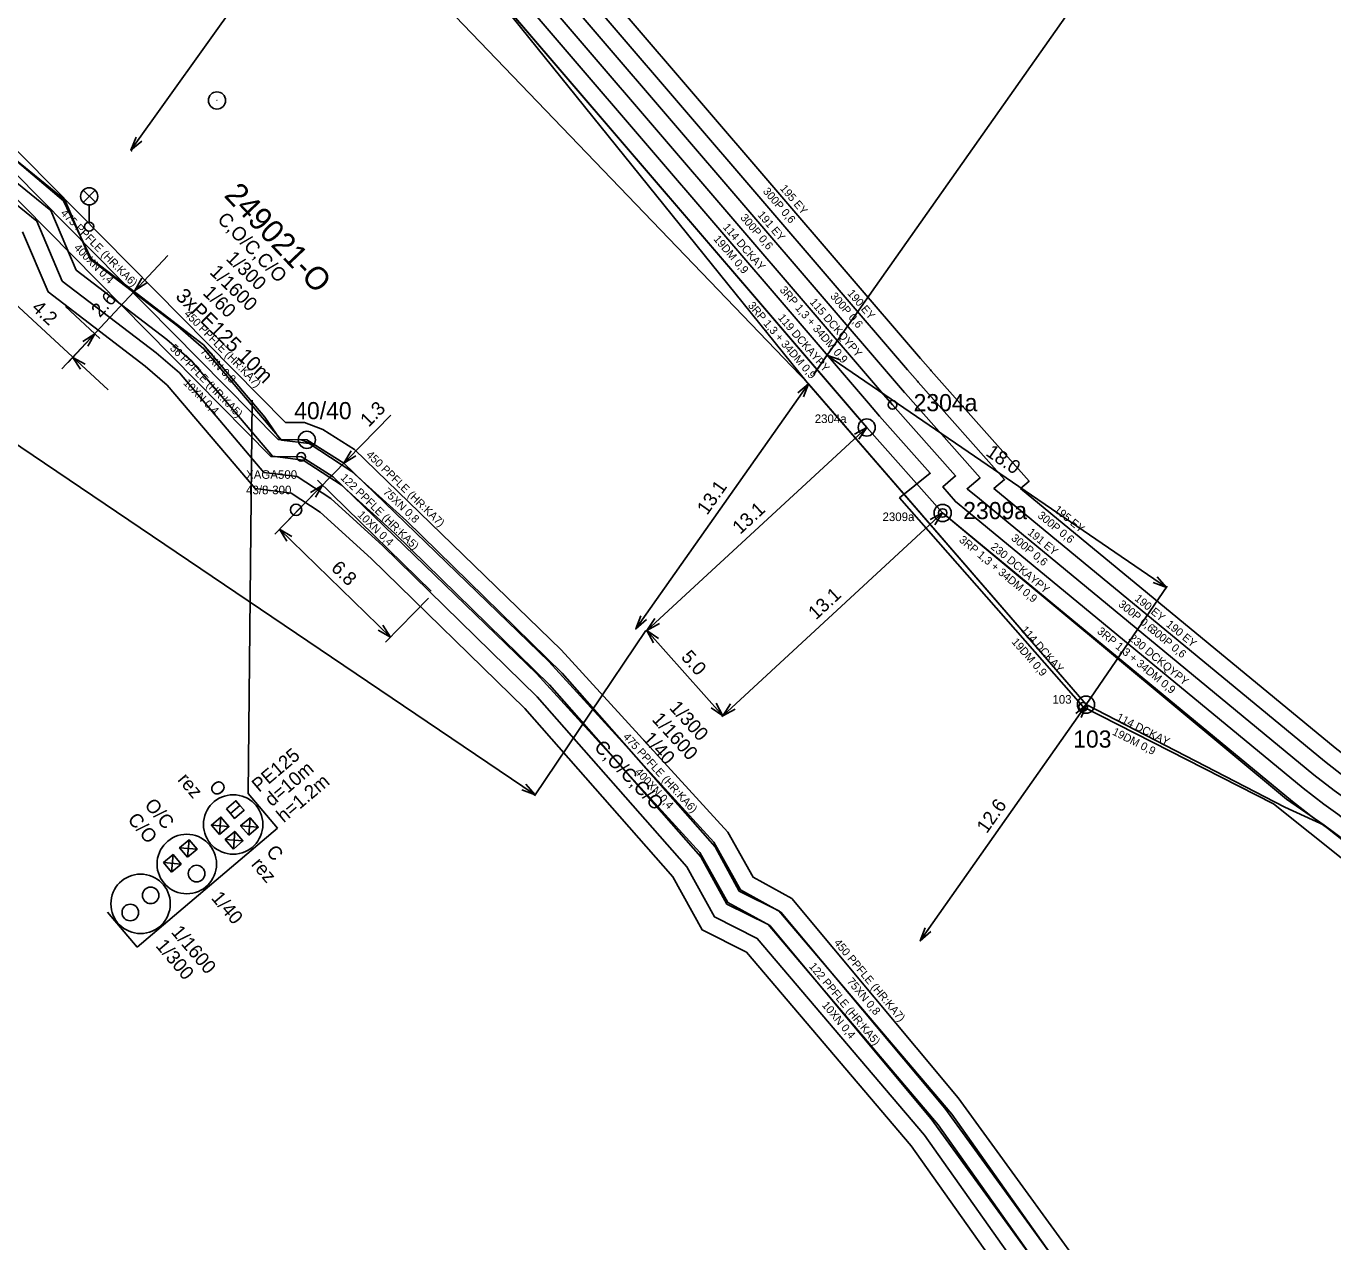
# Model space of a CAD drawing. Extents: x -756413 to -755757, y -1139003 to -1138237.
# Drawn here: x -756156 to -756098.8, y -1138473.1 to -1138419.9 of the extents above; entities that cross this region are included whole.
import ezdxf

# ---------------------------------------------------------------- set-up
doc = ezdxf.new("R2010")
doc.units = 0
for name, color, linetype in [('f001_pol_znacky', 7, 'Continuous'), ('f002_inz_znacky_mimo_TO2', 7, 'Continuous'), ('f003_opt_sit_texty', 7, 'Continuous'), ('f004_popis_kab_zil', 7, 'Continuous'), ('f004_popisy_mts', 7, 'Continuous'), ('f004_rezervy_spojky', 7, 'Continuous'), ('f006_osa_trasy', 7, 'Continuous'), ('f006_stp_koty', 7, 'Continuous'), ('f006_stp_linie', 7, 'Continuous'), ('f006_stp_texty', 7, 'Continuous'), ('f007_rezkynet_linie', 7, 'Continuous'), ('f007_rezkynet_texty', 7, 'Continuous'), ('f007_rezkynet_znacky', 7, 'Continuous'), ('f307_kabel_metal', 7, 'Continuous'), ('f307_kabel_metal_ann', 7, 'Continuous'), ('f307_spojka_metal', 7, 'Continuous'), ('f307_spojka_metal_ann', 7, 'Continuous'), ('f309_trubka', 7, 'Continuous')]:
    doc.layers.add(name, color=color, linetype=linetype)

msp = doc.modelspace()

# ---------------------------------------------------------------- linework, layer by layer
at = {"layer": 'f001_pol_znacky'}
for radius in [0.375, 0.0005]:
    msp.add_circle((-756147.61, -1138423.181), radius, dxfattribs=at)
at = {"layer": 'f002_inz_znacky_mimo_TO2'}
for p, q in [((-756153.464, -1138427.638), (-756152.936, -1138427.11)), ((-756152.928, -1138427.635), (-756153.456, -1138427.106)), ((-756153.2, -1138427.75), (-756153.2, -1138428.5))]:
    msp.add_line(p, q, dxfattribs=at)
for centre, radius in [((-756153.2, -1138427.375), 0.375), ((-756153.2, -1138428.7), 0.2), ((-756144.15, -1138441.08), 0.25)]:
    msp.add_circle(centre, radius, dxfattribs=at)
at = {"layer": 'f004_rezervy_spojky'}
for centre in [(-756119.19, -1138437.48), (-756143.68, -1138438.02), (-756115.87, -1138441.22), (-756109.6, -1138449.6)]:
    msp.add_circle(centre, 0.375, dxfattribs=at)
at = {"layer": 'f006_osa_trasy'}
for p, q in [((-756136.41, -1138417.4), (-756119.19, -1138437.48)), ((-756119.19, -1138437.48), (-756115.87, -1138441.22))]:
    msp.add_line(p, q, dxfattribs=at)
for points in [[(-756195.84, -1138343.55), (-756185.35, -1138358.4), (-756177.88, -1138364.69), (-756170.53, -1138375.55), (-756161.61, -1138387.83), (-756142.93, -1138413.51), (-756121.74, -1138435.57), (-756109.6, -1138449.6), (-756100.9, -1138454.08), (-756099.19, -1138454.87), (-756076.56, -1138471.66)], [(-756136.41, -1138417.4), (-756121.8, -1138435.51), (-756109.6, -1138449.6)], [(-756143.68, -1138438.02), (-756144.85, -1138438.01), (-756145.52, -1138437.03), (-756148.2, -1138433.87), (-756151.23, -1138431.54), (-756153.11, -1138430.11), (-756154.32, -1138427.57), (-756160.56, -1138422.3)], [(-756079.28, -1138533.22), (-756083.62, -1138524.47), (-756085.4, -1138521.04), (-756086.81, -1138519.72), (-756086.88, -1138518.13), (-756092.96, -1138505.67), (-756099.43, -1138492.74), (-756100.61, -1138491.98), (-756101.14, -1138489.58), (-756106.33, -1138480.26), (-756115.78, -1138467.25), (-756122.95, -1138458.67), (-756124.71, -1138457.7), (-756125.88, -1138455.62), (-756133.1, -1138447.72), (-756142.06, -1138439.04), (-756143.68, -1138438.02)], [(-756115.87, -1138441.22), (-756100.83, -1138453.74), (-756099.19, -1138454.87)], [(-756109.6, -1138449.6), (-756100.9, -1138454.08), (-756099.19, -1138454.87)]]:
    msp.add_lwpolyline(points, dxfattribs=at)
at = {"layer": 'f006_stp_koty'}
for p, q in [((-756151.373, -1138425.361), (-756142.913, -1138413.521)), ((-756121.515, -1138435.17), (-756110.503, -1138419.53)), ((-756183.425, -1138419.972), (-756133.692, -1138453.538)), ((-756151.341, -1138425.384), (-756151.324, -1138425.396)), ((-756154.392, -1138434.918), (-756149.763, -1138429.965)), ((-756158.555, -1138430.127), (-756152.369, -1138435.84)), ((-756154.24, -1138432.185), (-756152.739, -1138433.589)), ((-756153.162, -1138433.604), (-756154.115, -1138434.636)), ((-756121.481, -1138435.121), (-756120.895, -1138434.265)), ((-756120.929, -1138434.315), (-756106.084, -1138444.472)), ((-756129.294, -1138446.289), (-756121.73, -1138435.569)), ((-756144.46, -1138441.505), (-756140.011, -1138436.938)), ((-756128.803, -1138446.355), (-756119.19, -1138437.48)), ((-756143.204, -1138440.215), (-756145.084, -1138442.146)), ((-756138.236, -1138444.636), (-756143.21, -1138439.791)), ((-756125.485, -1138450.09), (-756115.872, -1138441.215)), ((-756144.875, -1138441.931), (-756140.024, -1138446.657)), ((-756109.586, -1138449.59), (-756106.05, -1138444.423)), ((-756138.353, -1138444.941), (-756140.233, -1138446.872)), ((-756128.851, -1138446.364), (-756133.726, -1138453.587)), ((-756128.802, -1138446.354), (-756128.847, -1138446.394)), ((-756128.802, -1138446.354), (-756125.484, -1138450.089)), ((-756116.851, -1138459.931), (-756109.585, -1138449.59)), ((-756125.484, -1138450.089), (-756125.529, -1138450.129))]:
    msp.add_line(p, q, dxfattribs=at)
for points in [[(-756150.902, -1138424.96), (-756151.373, -1138425.361), (-756151.146, -1138424.785)], [(-756150.677, -1138431.163), (-756151.197, -1138431.499), (-756150.896, -1138430.958)], [(-756153.477, -1138433.719), (-756152.958, -1138433.384), (-756153.258, -1138433.924)], [(-756153.573, -1138434.933), (-756153.912, -1138434.416), (-756153.369, -1138434.712)], [(-756120.518, -1138434.777), (-756120.929, -1138434.315), (-756120.349, -1138434.53)], [(-756122.198, -1138435.972), (-756121.73, -1138435.569), (-756121.953, -1138436.145)], [(-756119.732, -1138437.776), (-756119.19, -1138437.48), (-756119.529, -1138437.997)], [(-756141.532, -1138438.714), (-756142.059, -1138439.04), (-756141.747, -1138438.505)], [(-756143.521, -1138440.326), (-756142.995, -1138440.001), (-756143.306, -1138440.535)], [(-756116.414, -1138441.511), (-756115.872, -1138441.215), (-756116.211, -1138441.732)], [(-756144.549, -1138442.457), (-756144.875, -1138441.931), (-756144.34, -1138442.242)], [(-756106.494, -1138444.009), (-756106.084, -1138444.472), (-756106.663, -1138444.256)], [(-756128.825, -1138445.885), (-756129.294, -1138446.289), (-756129.07, -1138445.712)], [(-756128.26, -1138446.058), (-756128.803, -1138446.355), (-756128.463, -1138445.837)], [(-756140.349, -1138446.13), (-756140.024, -1138446.657), (-756140.558, -1138446.345)], [(-756128.515, -1138446.902), (-756128.802, -1138446.354), (-756128.291, -1138446.702)], [(-756125.77, -1138449.54), (-756125.484, -1138450.089), (-756125.994, -1138449.74)], [(-756124.942, -1138449.793), (-756125.485, -1138450.09), (-756125.145, -1138449.572)], [(-756110.052, -1138449.994), (-756109.585, -1138449.59), (-756109.807, -1138450.167)], [(-756134.105, -1138453.078), (-756133.692, -1138453.538), (-756134.273, -1138453.326)], [(-756116.383, -1138459.526), (-756116.851, -1138459.931), (-756116.628, -1138459.353)]]:
    msp.add_lwpolyline(points, dxfattribs=at)
at = {"layer": 'f006_stp_linie'}
msp.add_lwpolyline([(-756151.23, -1138431.54), (-756148.2, -1138433.87), (-756145.52, -1138437.03)], dxfattribs=at)
at = {"layer": 'f007_rezkynet_linie'}
msp.add_line((-756146.25, -1138453.48), (-756146.07, -1138436.29), dxfattribs=at)
at = {"layer": 'f007_rezkynet_znacky'}
for p, q in [((-756144.958, -1138455.007), (-756146.25, -1138453.48)), ((-756147.502, -1138455.284), (-756147.438, -1138454.516)), ((-756146.222, -1138455.314), (-756146.158, -1138454.546)), ((-756151.103, -1138460.207), (-756144.958, -1138455.007)), ((-756147.086, -1138454.932), (-756147.854, -1138454.868)), ((-756146.892, -1138455.914), (-756146.828, -1138455.146)), ((-756145.806, -1138454.962), (-756146.574, -1138454.898)), ((-756148.892, -1138456.274), (-756148.828, -1138455.506)), ((-756146.476, -1138455.562), (-756147.244, -1138455.498)), ((-756149.592, -1138456.924), (-756149.528, -1138456.156)), ((-756148.476, -1138455.922), (-756149.244, -1138455.858)), ((-756149.176, -1138456.572), (-756149.944, -1138456.508)), ((-756152.395, -1138458.68), (-756151.103, -1138460.207))]:
    msp.add_line(p, q, dxfattribs=at)
for points in [[(-756147.194, -1138454.158), (-756147.018, -1138454.366), (-756146.602, -1138454.014), (-756146.778, -1138453.806)], [(-756147.018, -1138454.366), (-756146.842, -1138454.574), (-756146.426, -1138454.222), (-756146.602, -1138454.014)], [(-756147.502, -1138455.284), (-756147.854, -1138454.868), (-756147.438, -1138454.516), (-756147.086, -1138454.932)], [(-756146.222, -1138455.314), (-756146.574, -1138454.898), (-756146.158, -1138454.546), (-756145.806, -1138454.962)], [(-756146.892, -1138455.914), (-756147.244, -1138455.498), (-756146.828, -1138455.146), (-756146.476, -1138455.562)], [(-756148.892, -1138456.274), (-756149.244, -1138455.858), (-756148.828, -1138455.506), (-756148.476, -1138455.922)], [(-756149.592, -1138456.924), (-756149.944, -1138456.508), (-756149.528, -1138456.156), (-756149.176, -1138456.572)]]:
    msp.add_lwpolyline(points, close=True, dxfattribs=at)
for centre, radius in [((-756146.9, -1138454.84), 1.3), ((-756148.93, -1138456.57), 1.3), ((-756148.5, -1138456.99), 0.363), ((-756150.95, -1138458.31), 1.3), ((-756150.51, -1138457.94), 0.363), ((-756151.4, -1138458.69), 0.363)]:
    msp.add_circle(centre, radius, dxfattribs=at)
at = {"layer": 'f307_kabel_metal'}
for points in [[(-756192.101, -1138346.002), (-756192.062, -1138346.05), (-756190.373, -1138348.218), (-756182.872, -1138356.623), (-756182.86, -1138356.637), (-756176.354, -1138364.322), (-756167.508, -1138377.346), (-756165.298, -1138380.468), (-756164.869, -1138381.062), (-756161.006, -1138386.276), (-756135.291, -1138416.4), (-756134.804, -1138416.968), (-756118.54, -1138435.935), (-756118.06, -1138436.494)], [(-756191.54, -1138349.16), (-756184.509, -1138357.041), (-756184.01, -1138357.6), (-756177.55, -1138365.23), (-756168.74, -1138378.2), (-756166.518, -1138381.34), (-756166.079, -1138381.948), (-756162.18, -1138387.21), (-756136.431, -1138417.375), (-756135.943, -1138417.944), (-756119.678, -1138436.911), (-756119.19, -1138437.48), (-756115.87, -1138441.22)], [(-756183.432, -1138357.122), (-756176.952, -1138364.776), (-756168.124, -1138377.773), (-756165.908, -1138380.904), (-756165.474, -1138381.505), (-756161.593, -1138386.743), (-756135.861, -1138416.887), (-756135.374, -1138417.456), (-756119.109, -1138436.423), (-756118.625, -1138436.987), (-756116.412, -1138439.48), (-756117.75, -1138440.561), (-756109.723, -1138449.702)], [(-756159.245, -1138384.875), (-756133.581, -1138414.937), (-756133.096, -1138415.504), (-756116.833, -1138434.471), (-756116.406, -1138434.968), (-756116.374, -1138435.005), (-756112.089, -1138439.831), (-756112.46, -1138440.144), (-756098.699, -1138451.492), (-756097.846, -1138452.155), (-756097.226, -1138452.599), (-756075.319, -1138469.96), (-756074.731, -1138470.426), (-756073.006, -1138471.794), (-756072.418, -1138472.26), (-756071.808, -1138472.743), (-756069.341, -1138476.062)], [(-756159.832, -1138385.342), (-756134.151, -1138415.425), (-756133.665, -1138415.992), (-756117.402, -1138434.959), (-756116.972, -1138435.46), (-756116.936, -1138435.501), (-756113.16, -1138439.754), (-756113.63, -1138440.151), (-756099.168, -1138452.077), (-756098.295, -1138452.756), (-756097.678, -1138453.198), (-756075.785, -1138470.548), (-756075.197, -1138471.014), (-756073.472, -1138472.382)], [(-756160.419, -1138385.809), (-756134.721, -1138415.912), (-756134.235, -1138416.48), (-756117.971, -1138435.447), (-756117.539, -1138435.95), (-756117.499, -1138435.996), (-756114.231, -1138439.677), (-756114.803, -1138440.16), (-756114.786, -1138440.18), (-756114.258, -1138440.606), (-756099.637, -1138452.663), (-756098.744, -1138453.357), (-756098.13, -1138453.797), (-756076.201, -1138471.176)], [(-756186.311, -1138407.814), (-756178.928, -1138410.846), (-756170.736, -1138415.474), (-756170.095, -1138415.966), (-756161.015, -1138422.896), (-756160.443, -1138423.38), (-756145.248, -1138438.757), (-756143.928, -1138438.768)], [(-756159.423, -1138422.278), (-756144.616, -1138437.262), (-756143.781, -1138437.269), (-756142.977, -1138437.576), (-756141.594, -1138438.447), (-756132.562, -1138447.197), (-756125.268, -1138455.177), (-756124.161, -1138457.146), (-756122.465, -1138458.081), (-756115.188, -1138466.789), (-756105.697, -1138479.856), (-756100.431, -1138489.311), (-756099.944, -1138491.517), (-756098.851, -1138492.221), (-756092.288, -1138505.338), (-756086.138, -1138517.941)], [(-756159.933, -1138422.829), (-756144.932, -1138438.01), (-756143.922, -1138438.018), (-756143.314, -1138438.25), (-756142.06, -1138439.04), (-756133.1, -1138447.72), (-756125.88, -1138455.62), (-756124.71, -1138457.7), (-756122.95, -1138458.67), (-756115.78, -1138467.25), (-756106.33, -1138480.26), (-756101.14, -1138489.58), (-756100.61, -1138491.98), (-756099.43, -1138492.74), (-756092.96, -1138505.67), (-756086.88, -1138518.13)], [(-756118.06, -1138436.494), (-756115.302, -1138439.6), (-756115.868, -1138440.078), (-756115.309, -1138440.722), (-756114.732, -1138441.187), (-756100.106, -1138453.248), (-756099.193, -1138453.958), (-756098.582, -1138454.396), (-756073.437, -1138474.323), (-756067.467, -1138482.356), (-756067.103, -1138482.845), (-756053.982, -1138492.668), (-756043.489, -1138502.85), (-756028.271, -1138519.778)], [(-756143.928, -1138438.768), (-756143.92, -1138438.755), (-756142.526, -1138439.633), (-756133.638, -1138448.243), (-756126.492, -1138456.063), (-756125.259, -1138458.254), (-756123.435, -1138459.259), (-756116.372, -1138467.711), (-756106.963, -1138480.664), (-756101.849, -1138489.849), (-756101.276, -1138492.443), (-756100.009, -1138493.259), (-756093.632, -1138506.002), (-756087.622, -1138518.319), (-756087.546, -1138520.059), (-756086.006, -1138521.5), (-756084.289, -1138524.809), (-756080.078, -1138533.3), (-756080.006, -1138533.447), (-756082.212, -1138534.345), (-756082.897, -1138534.615), (-756087.547, -1138536.319), (-756088.749, -1138536.759)], [(-756115.87, -1138441.22), (-756100.575, -1138453.833), (-756099.642, -1138454.559), (-756099.033, -1138454.995), (-756073.98, -1138474.85), (-756068.069, -1138482.803), (-756067.64, -1138483.38), (-756054.47, -1138493.24), (-756044.03, -1138503.37), (-756028.82, -1138520.29), (-756023.791, -1138525.491), (-756023.27, -1138526.03), (-756020.86, -1138528.62), (-756019.97, -1138529.61), (-756019.66, -1138535.02), (-756014.34, -1138539.73), (-756002.7, -1138549.54), (-756020.63, -1138568.61), (-756010.79, -1138582.3), (-756003.44, -1138591.94)], [(-756109.723, -1138449.702), (-756101.395, -1138453.937), (-756074.523, -1138475.377), (-756068.671, -1138483.25), (-756068.177, -1138483.915), (-756054.958, -1138493.812), (-756044.571, -1138503.89), (-756040.521, -1138508.396)]]:
    msp.add_lwpolyline(points, dxfattribs=at)
at = {"layer": 'f307_spojka_metal'}
for centre in [(-756118.06, -1138436.494), (-756143.928, -1138438.768), (-756115.87, -1138441.22), (-756109.723, -1138449.702)]:
    msp.add_circle(centre, 0.188, dxfattribs=at)
at = {"layer": 'f309_trubka'}
for points in [[(-756161.932, -1138421.301), (-756154.261, -1138427.534), (-756153.158, -1138430.126), (-756149.322, -1138433.052), (-756148.183, -1138434.04), (-756144.791, -1138438.031), (-756143.576, -1138438.183), (-756141.715, -1138439.399), (-756139.323, -1138441.566), (-756132.516, -1138448.22), (-756125.826, -1138455.825), (-756124.763, -1138457.754), (-756123.035, -1138458.618), (-756115.475, -1138467.51), (-756110.292, -1138474.826), (-756106.437, -1138480.147), (-756101.083, -1138489.621), (-756100.684, -1138491.949), (-756099.355, -1138492.88), (-756094.371, -1138502.989), (-756088.162, -1138515.503)], [(-756162.398, -1138421.889), (-756154.878, -1138427.999), (-756153.77, -1138430.602), (-756149.796, -1138433.634), (-756148.718, -1138434.569), (-756145.174, -1138438.739), (-756143.841, -1138438.906), (-756142.175, -1138439.995), (-756139.837, -1138442.112), (-756133.06, -1138448.737), (-756126.443, -1138456.259), (-756125.307, -1138458.32), (-756123.507, -1138459.22), (-756116.068, -1138467.971), (-756110.902, -1138475.263), (-756107.069, -1138480.553), (-756101.8, -1138489.876), (-756101.37, -1138492.384), (-756099.943, -1138493.384), (-756095.043, -1138503.322), (-756088.833, -1138515.838)], [(-756162.864, -1138422.477), (-756155.495, -1138428.464), (-756154.382, -1138431.078), (-756150.27, -1138434.216), (-756149.253, -1138435.098), (-756145.557, -1138439.447), (-756144.106, -1138439.629), (-756142.635, -1138440.591), (-756140.351, -1138442.658), (-756133.604, -1138449.254), (-756127.06, -1138456.693), (-756125.851, -1138458.886), (-756123.979, -1138459.822), (-756116.661, -1138468.432), (-756111.512, -1138475.7), (-756107.701, -1138480.959), (-756102.517, -1138490.131), (-756102.056, -1138492.819), (-756100.531, -1138493.888), (-756095.715, -1138503.655), (-756089.504, -1138516.173)], [(-756156.112, -1138428.929), (-756154.994, -1138431.554), (-756150.744, -1138434.798), (-756149.788, -1138435.627), (-756145.94, -1138440.155), (-756144.371, -1138440.352), (-756143.095, -1138441.187), (-756140.865, -1138443.204), (-756134.148, -1138449.771), (-756127.677, -1138457.127), (-756126.395, -1138459.452), (-756124.451, -1138460.424), (-756117.254, -1138468.893), (-756112.122, -1138476.137), (-756108.333, -1138481.365), (-756103.234, -1138490.386), (-756102.742, -1138493.254), (-756101.119, -1138494.392), (-756096.387, -1138503.988), (-756090.175, -1138516.508)]]:
    msp.add_lwpolyline(points, dxfattribs=at)

# ---------------------------------------------------------------- texts
at = {"layer": 'f003_opt_sit_texty'}
for s, height, rotation, p in [('249021-O', 1, 313.5, (-756147.34, -1138427.36)), ('C,O/C,C/O', 0.6, 314.3, (-756147.63, -1138428.42)), ('C,O/C,C/O', 0.6, 314.3, (-756131.15, -1138451.5))]:
    msp.add_text(s, height=height, rotation=rotation, dxfattribs=at).set_placement(p)
at = {"layer": 'f004_popis_kab_zil'}
for s, rotation, p in [('1/300', 315.77, (-756147.25, -1138430.13)), ('1/1600', 315.77, (-756147.96, -1138430.73)), ('1/60', 315.77, (-756148.26, -1138431.64)), ('1/1600', 312.42, (-756128.62, -1138450.27)), ('1/300', 312.42, (-756127.86, -1138449.76)), ('1/40', 312.42, (-756129.02, -1138451.12))]:
    msp.add_text(s, height=0.6, rotation=rotation, dxfattribs=at).set_placement(p)
at = {"layer": 'f004_popisy_mts'}
for s, p in [('2304a', (-756117.14, -1138436.77)), ('40/40', (-756144.23, -1138437.12)), ('2309a', (-756114.97, -1138441.49)), ('103', (-756110.16, -1138451.48))]:
    msp.add_text(s, height=0.75, dxfattribs=at).set_placement(p)
at = {"layer": 'f006_stp_koty'}
for s, rotation, p in [('2.6', 46.94, (-756152.731, -1138432.702)), ('4.2', 317.27, (-756155.755, -1138432.304)), ('1.3', 45.75, (-756140.974, -1138437.496)), ('18.0', 325.62, (-756114.022, -1138438.677)), ('13.1', 54.79, (-756126.172, -1138441.344)), ('13.1', 42.71, (-756124.728, -1138442.184)), ('6.8', 315.75, (-756142.656, -1138443.673)), ('13.1', 42.71, (-756121.41, -1138445.919)), ('5.0', 311.62, (-756127.342, -1138447.545)), ('12.6', 54.91, (-756113.941, -1138455.267))]:
    msp.add_text(s, height=0.6, rotation=rotation, dxfattribs=at).set_placement(p)
at = {"layer": 'f006_stp_texty'}
msp.add_text('3xPE125 10m', height=0.65, rotation=315.77, dxfattribs=at).set_placement((-756149.46, -1138431.79))
at = {"layer": 'f007_rezkynet_texty'}
for s, rotation, p in [('PE125', 40.23, (-756145.77, -1138453.46)), ('d=10m', 40.23, (-756145.21, -1138454.09)), ('rez', 310.23, (-756149.36, -1138452.9)), ('h=1.2m', 40.23, (-756144.69, -1138454.79)), ('O', 310.23, (-756148, -1138453.2)), ('O/C', 310.23, (-756150.81, -1138454.01)), ('C/O', 310.23, (-756151.55, -1138454.64)), ('C', 310.23, (-756145.49, -1138456.05)), ('rez', 310.23, (-756146.14, -1138456.6)), ('1/40', 310.23, (-756147.89, -1138458.07)), ('1/1600', 310.23, (-756149.64, -1138459.56)), ('1/300', 310.23, (-756150.32, -1138460.16))]:
    msp.add_text(s, height=0.6, rotation=rotation, dxfattribs=at).set_placement(p)
at = {"layer": 'f307_kabel_metal_ann'}
for s, rotation, p in [(' 300P 0,6', 310.61, (-756123.839, -1138427.069)), ('195 EY', 310.61, (-756123.005, -1138427.042)), ('475 PPFLE (HR:KA6)', 314.66, (-756154.476, -1138428.139)), (' 300P 0,6', 310.61, (-756124.823, -1138428.224)), ('191 EY', 310.61, (-756123.989, -1138428.197)), ('114 DCKAY', 310.61, (-756125.503, -1138428.735)), (' 19DM 0,9', 310.61, (-756125.998, -1138429.157)), (' 400XN 0,4', 314.66, (-756153.983, -1138429.562)), (' 3RP 1,3 + 34DM 0,9', 310.61, (-756123.104, -1138431.381)), (' 300P 0,6', 310.61, (-756120.893, -1138431.655)), ('190 EY', 310.61, (-756120.059, -1138431.628)), (' 3RP 1,3 + 34DM 0,9', 310.61, (-756124.493, -1138432.064)), ('115 DCKQYPY', 310.61, (-756121.705, -1138432.013)), ('450 PPFLE (HR:KA7)', 314.66, (-756149.069, -1138432.543)), ('119 DCKAYPY', 310.61, (-756123.094, -1138432.696)), ('56 PPFLE (HR:KA5)', 314.66, (-756149.694, -1138434.045)), (' 75XN 0,8', 314.66, (-756148.454, -1138434.089)), (' 10XN 0,4', 314.66, (-756149.201, -1138435.468)), ('450 PPFLE (HR:KA7)', 315.91, (-756141.108, -1138438.709)), ('122 PPFLE (HR:KA5)', 315.91, (-756142.23, -1138439.711)), (' 75XN 0,8', 315.91, (-756140.46, -1138440.242)), (' 10XN 0,4', 315.91, (-756141.582, -1138441.244)), (' 300P 0,6', 320.49, (-756111.845, -1138441.299)), ('195 EY', 320.49, (-756111.029, -1138441.129)), ('191 EY', 320.49, (-756112.185, -1138442.121)), (' 3RP 1,3 + 34DM 0,9', 320.22, (-756115.281, -1138442.361)), ('230 DCKAYPY', 320.22, (-756113.796, -1138442.751)), (' 300P 0,6', 320.49, (-756113.001, -1138442.291)), ('190 EY', 320.49, (-756107.5, -1138445.011)), (' 300P 0,6', 320.49, (-756108.316, -1138445.181)), ('190 EY', 320.49, (-756106.127, -1138446.144)), ('114 DCKAY', 311.29, (-756112.47, -1138446.346)), (' 3RP 1,3 + 34DM 0,9', 320.49, (-756109.243, -1138446.362)), ('230 DCKQYPY', 320.49, (-756107.756, -1138446.745)), (' 300P 0,6', 320.49, (-756106.943, -1138446.314)), (' 19DM 0,9', 311.29, (-756112.959, -1138446.774)), ('114 DCKAY', 333.05, (-756108.299, -1138450.258)), ('475 PPFLE (HR:KA6)', 312.42, (-756129.874, -1138451.028)), (' 19DM 0,9', 333.05, (-756108.595, -1138450.837)), (' 400XN 0,4', 312.42, (-756129.437, -1138452.469)), ('450 PPFLE (HR:KA7)', 309.88, (-756120.645, -1138460.024)), ('122 PPFLE (HR:KA5)', 309.88, (-756121.737, -1138461.057)), (' 75XN 0,8', 309.88, (-756120.161, -1138461.617)), (' 10XN 0,4', 309.88, (-756121.253, -1138462.65))]:
    msp.add_text(s, height=0.35, rotation=rotation, dxfattribs=at).set_placement(p)
at = {"layer": 'f307_spojka_metal_ann'}
for s, p in [('2304a', (-756121.465, -1138437.287)), ('XAGA500', (-756146.335, -1138439.726)), ('43/8-300', (-756146.335, -1138440.401)), ('2309a', (-756118.5, -1138441.574)), ('103', (-756111.067, -1138449.558))]:
    msp.add_text(s, height=0.375, dxfattribs=at).set_placement(p)

doc.saveas('drawing.dxf')
